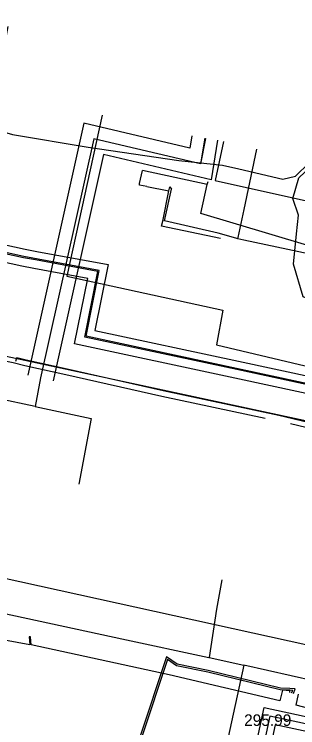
# Model space of a CAD drawing. Extents: x -598233 to -596890, y -1157848 to -1156431.
# Drawn here: x -597028.98 to -597009.35, y -1156707.55 to -1156658.09 of the extents above; entities that cross this region are included whole.
import ezdxf

# ---------------------------------------------------------------- set-up
doc = ezdxf.new("R2010")
doc.units = 0
for name, color, linetype in [('Vrstva 12', 7, 'Continuous'), ('Vrstva 13', 7, 'Continuous'), ('Vrstva 16', 7, 'Continuous'), ('Vrstva 19', 7, 'Continuous'), ('Vrstva 25', 7, 'Continuous'), ('Vrstva 26', 7, 'Continuous'), ('Vrstva 37', 7, 'Continuous'), ('Vrstva 38', 7, 'Continuous'), ('Vrstva 42', 7, 'Continuous'), ('Vrstva 55', 7, 'Continuous'), ('Vrstva 9', 7, 'Continuous')]:
    doc.layers.add(name, color=color, linetype=linetype)

msp = doc.modelspace()

# ---------------------------------------------------------------- linework, layer by layer
at = {"layer": 'Vrstva 12'}
for points in [[(-597002.27, -1156687.69), (-597020.83, -1156683.69), (-597091.98, -1156668.39), (-597150.87, -1156655.17)], [(-597022.89, -1156665.09), (-597025.34, -1156676.24), (-597014.53, -1156678.61), (-597014.97, -1156681), (-596999.57, -1156684.65), (-597002.1, -1156686.88), (-597002.27, -1156687.69)], [(-597014.5, -1156666.92), (-597015.07, -1156669.61), (-596995.45, -1156673.99), (-596998.55, -1156688.49)]]:
    msp.add_lwpolyline(points, dxfattribs=at)
at = {"layer": 'Vrstva 13'}
msp.add_lwpolyline([(-596999.775, -1156679.933), (-597001.811, -1156689.836), (-597004.47, -1156702.751), (-597007.229, -1156702.144), (-597081.841, -1156685.694), (-597084.22, -1156685.17)], dxfattribs=at)
at = {"layer": 'Vrstva 16'}
for points in [[(-596890.462, -1156658.167), (-596900.13, -1156664.59), (-596900.58, -1156666.8), (-596902.94, -1156666.3), (-596908.67, -1156669.34), (-596927.34, -1156681.23), (-596931.7, -1156684.23), (-596932.66, -1156688.6), (-596936.9, -1156687.83), (-596940.03, -1156690), (-596981.04, -1156681.27), (-596997, -1156677.6), (-597016.06, -1156671.9), (-597015.61, -1156669.9)], [(-597019.79, -1156670.04), (-597020.31, -1156669.94), (-597020.3, -1156669.83), (-597020.1, -1156668.92)], [(-597015.61, -1156669.9), (-597020.1, -1156668.92)], [(-597015.61, -1156669.9), (-597015.56, -1156669.68)], [(-597019.79, -1156670.04), (-597018.27, -1156670.33), (-597018.21, -1156670.06), (-597018.1, -1156670.21)], [(-597014.69, -1156673.64), (-597018.79, -1156672.78), (-597018.7, -1156672.43), (-597018.27, -1156670.33)]]:
    msp.add_lwpolyline(points, dxfattribs=at)
at = {"layer": 'Vrstva 19'}
for points in [[(-597013.067, -1156671.63), (-597012.17, -1156667.44)], [(-597014.86, -1156673.27), (-597018.58, -1156672.42), (-597018.1, -1156670.21)], [(-597013.5, -1156673.65), (-597013.48, -1156673.56), (-597013.067, -1156671.63)], [(-596990.71, -1156678.66), (-596996.77, -1156677.21), (-597013.07, -1156673.75), (-597013.5, -1156673.65), (-597013.64, -1156673.62), (-597014.86, -1156673.27)]]:
    msp.add_lwpolyline(points, dxfattribs=at)
at = {"layer": 'Vrstva 25'}
for points in [[(-596997.226, -1156682.65), (-597001.716, -1156681.678), (-597002.463, -1156685.113), (-597013.575, -1156682.724), (-597024.093, -1156680.468), (-597023.184, -1156675.919), (-597027.517, -1156675.118), (-597028.333, -1156674.965), (-597054.148, -1156669.331), (-597061.952, -1156667.705), (-597087.165, -1156662.298), (-597112.173, -1156656.978)], [(-596994.388, -1156690.946), (-596998.378, -1156709.528), (-597011.29, -1156706.75), (-597019.515, -1156745.077), (-597014.714, -1156746.107)]]:
    msp.add_lwpolyline(points, dxfattribs=at)
at = {"layer": 'Vrstva 26'}
for points in [[(-597112.049, -1156656.391), (-597087.039, -1156661.711), (-597061.828, -1156667.118), (-597054.022, -1156668.745), (-597028.214, -1156674.377), (-597027.407, -1156674.529), (-597022.476, -1156675.44), (-597023.388, -1156680.005), (-597013.449, -1156682.137), (-597002.922, -1156684.401), (-597002.174, -1156680.964), (-596997.589, -1156681.958)], [(-596997.841, -1156683.131), (-597001.257, -1156682.391), (-597002.004, -1156685.826), (-597013.701, -1156683.31), (-597024.797, -1156680.931), (-597023.892, -1156676.399), (-597027.627, -1156675.708), (-597028.452, -1156675.553), (-597054.273, -1156669.918), (-597062.076, -1156668.292), (-597087.29, -1156662.885), (-597112.298, -1156657.564)], [(-597014.819, -1156746.596), (-597020.109, -1156745.461), (-597011.674, -1156706.156), (-596998.762, -1156708.934), (-596994.982, -1156691.329)], [(-596994.004, -1156691.54), (-596997.994, -1156710.122), (-597010.906, -1156707.344), (-597018.921, -1156744.693), (-597014.609, -1156745.618)]]:
    msp.add_lwpolyline(points, dxfattribs=at)
at = {"layer": 'Vrstva 37'}
for p, q in [((-597027.533, -1156685.284), (-597073.576, -1156675.297)), ((-597027.164, -1156683.298), (-597027.533, -1156685.284))]:
    msp.add_line(p, q, dxfattribs=at)
for points in [[(-597015.785, -1156666.674), (-597016.08, -1156668.464), (-597023.474, -1156666.729), (-597027.164, -1156683.298)], [(-597015.739, -1156666.697), (-597016.08, -1156668.464), (-597023.474, -1156666.729), (-597027.164, -1156683.298)], [(-597027.533, -1156685.284), (-597023.663, -1156686.123), (-597024.505, -1156690.655)]]:
    msp.add_lwpolyline(points, dxfattribs=at)
at = {"layer": 'Vrstva 38'}
for points in [[(-597016.673, -1156666.528), (-597016.811, -1156667.368), (-597024.155, -1156665.645), (-597028.042, -1156683.102)], [(-597014.897, -1156666.82), (-597015.349, -1156669.56), (-597022.793, -1156667.813), (-597026.286, -1156683.494)]]:
    msp.add_lwpolyline(points, dxfattribs=at)
at = {"layer": 'Vrstva 42'}
for points in [[(-596999.24, -1156639.27), (-596988.29, -1156641.64), (-596994.55, -1156670.69), (-596991.12, -1156671.45), (-596991.86, -1156674.88), (-596995.26, -1156674.15), (-596996.88, -1156681.64), (-596997.19, -1156682.58), (-597001.78, -1156681.58), (-597002.53, -1156685.02), (-597024, -1156680.41), (-597023.09, -1156675.85), (-597028.32, -1156674.89), (-597031.8, -1156674.13), (-597035.14, -1156673.4), (-597042.6, -1156671.77), (-597056.5, -1156668.76), (-597065.96, -1156666.76), (-597073.93, -1156665.05), (-597082.87, -1156663.14), (-597088.13, -1156662.01), (-597096.4, -1156660.25), (-597103.15, -1156658.82)], [(-597029.433, -1156658.945), (-597030.322, -1156663.652), (-597030.56, -1156665.355), (-597030.433, -1156665.859), (-597030.064, -1156666.142), (-597029.096, -1156666.43), (-597023.853, -1156667.298), (-597017.578, -1156668.224), (-597014.568, -1156668.56), (-597013.426, -1156668.813), (-597010.387, -1156669.514), (-597009.502, -1156669.32), (-597008.563, -1156668.394), (-597007.061, -1156668.689), (-597005.222, -1156669.191)], [(-597015.74, -1156666.7), (-597016.08, -1156668.46), (-597023.47, -1156666.73), (-597027.16, -1156683.3)], [(-597007.82, -1156708.802), (-597006.731, -1156705.684), (-597004.651, -1156702.971), (-597003.718, -1156701.032), (-597002.366, -1156697.824), (-597001.674, -1156692.961), (-597001.344, -1156688.452), (-597001.315, -1156688.051), (-597001.075, -1156684.767), (-597000.458, -1156680.939), (-597000.534, -1156680.168), (-597001.025, -1156679.762), (-597002.023, -1156679.572), (-597006.158, -1156678.86), (-597008.972, -1156677.675), (-597009.651, -1156675.404), (-597009.445, -1156673.323), (-597009.299, -1156672.012), (-597009.679, -1156670.869), (-597009.274, -1156669.441), (-597008.442, -1156668.649), (-597006.9, -1156668.944), (-597005.266, -1156669.386)], [(-597045.183, -1156678.763), (-597037.102, -1156680.596), (-597029.059, -1156682.226), (-597028.237, -1156682.445), (-597025.403, -1156683.055), (-597018.763, -1156684.555), (-597011.614, -1156686.085)], [(-597028.866, -1156682.128), (-597028.805, -1156681.88), (-597028.143, -1156682.055), (-597025.317, -1156682.665), (-597018.677, -1156684.165), (-597010.668, -1156685.878), (-597003.017, -1156687.715), (-597001.315, -1156688.051), (-597000.917, -1156688.129), (-597000.511, -1156688.209), (-597000.112, -1156688.288), (-596999.702, -1156688.369), (-596999.397, -1156688.429), (-596999.308, -1156688.471), (-596998.232, -1156688.983), (-596998.22, -1156689.88), (-596999.025, -1156693.653), (-596999.285, -1156694.773), (-596999.585, -1156696.183), (-597000.198, -1156698.828), (-597000.478, -1156699.568), (-597000.609, -1156699.546)], [(-597000.566, -1156698.948), (-597000.393, -1156698.573), (-596999.975, -1156696.097), (-596999.675, -1156694.687), (-596999.415, -1156693.567), (-596998.62, -1156689.84), (-596998.628, -1156689.237), (-596999.339, -1156688.899), (-596999.523, -1156688.811), (-596999.731, -1156688.77), (-597000.141, -1156688.689), (-597000.541, -1156688.61), (-597000.946, -1156688.53), (-597001.344, -1156688.452), (-597003.103, -1156688.105), (-597009.855, -1156686.483)]]:
    msp.add_lwpolyline(points, dxfattribs=at)
at = {"layer": 'Vrstva 55'}
for points in [[(-596993.714, -1156680.787), (-596994.29, -1156680.764), (-596994.71, -1156685.2), (-596994.41, -1156685.89), (-596992.16, -1156686.62), (-596991.98, -1156687.17), (-596993.871, -1156696.572), (-596994.535, -1156699.73), (-596995.024, -1156700.209), (-596996.25, -1156699.86), (-596996.283, -1156699.975), (-596995.06, -1156700.323), (-596994.99, -1156700.64), (-596996.78, -1156703.3), (-596999.56, -1156705.93), (-597002.01, -1156707.11), (-597004.2, -1156707.38), (-597009.45, -1156705.978), (-597009.306, -1156705.216)], [(-597010.399, -1156704.948), (-597010.579, -1156705.679), (-597018.26, -1156703.87), (-597027.809, -1156701.811), (-597027.85, -1156701.246), (-597027.95, -1156701.254), (-597027.911, -1156701.791), (-597035.69, -1156700.36)], [(-597009.652, -1156705.166), (-597009.517, -1156704.86), (-597009.896, -1156704.82), (-597010.552, -1156704.8), (-597015.557, -1156703.581), (-597017.689, -1156703.136), (-597018.442, -1156702.637), (-597020.277, -1156708.202), (-597021.038, -1156710.816), (-597021.688, -1156713.966), (-597022.998, -1156718.736), (-597023.175, -1156719.582), (-597023.49, -1156719.933), (-597031.444, -1156720.911)], [(-597009.77, -1156705.135), (-597009.694, -1156704.962), (-597009.904, -1156704.94), (-597010.568, -1156704.92), (-597015.583, -1156703.699), (-597017.736, -1156703.249), (-597018.378, -1156702.823), (-597020.163, -1156708.238), (-597020.922, -1156710.844), (-597021.572, -1156713.994), (-597022.882, -1156718.764), (-597023.065, -1156719.638), (-597023.43, -1156720.047), (-597031.416, -1156721.029)], [(-597009.899, -1156705.107), (-597009.891, -1156704.979), (-597010.399, -1156704.948)]]:
    msp.add_lwpolyline(points, dxfattribs=at)
at = {"layer": 'Vrstva 9'}
for p, q in [((-597014.608, -1156697.287), (-597014.969, -1156699.325)), ((-597014.969, -1156699.325), (-597015.476, -1156702.683)), ((-597013.083, -1156703.2), (-597023.448, -1156750.624)), ((-596982.507, -1156710.17), (-597013.083, -1156703.2))]:
    msp.add_line(p, q, dxfattribs=at)
msp.add_lwpolyline([(-597051.894, -1156694.817), (-597051.157, -1156694.976), (-597050.682, -1156695.079), (-597033.255, -1156698.848), (-597033.19, -1156698.862), (-597021.535, -1156701.376), (-597021.525, -1156701.378), (-597015.494, -1156702.679), (-597015.476, -1156702.683), (-597013.083, -1156703.2)], dxfattribs=at)

# ---------------------------------------------------------------- texts
at = {"layer": 'Vrstva 12'}
msp.add_text('295.99', height=0.8, dxfattribs=at).set_placement((-597013.063, -1156707.423))

doc.saveas('drawing.dxf')
